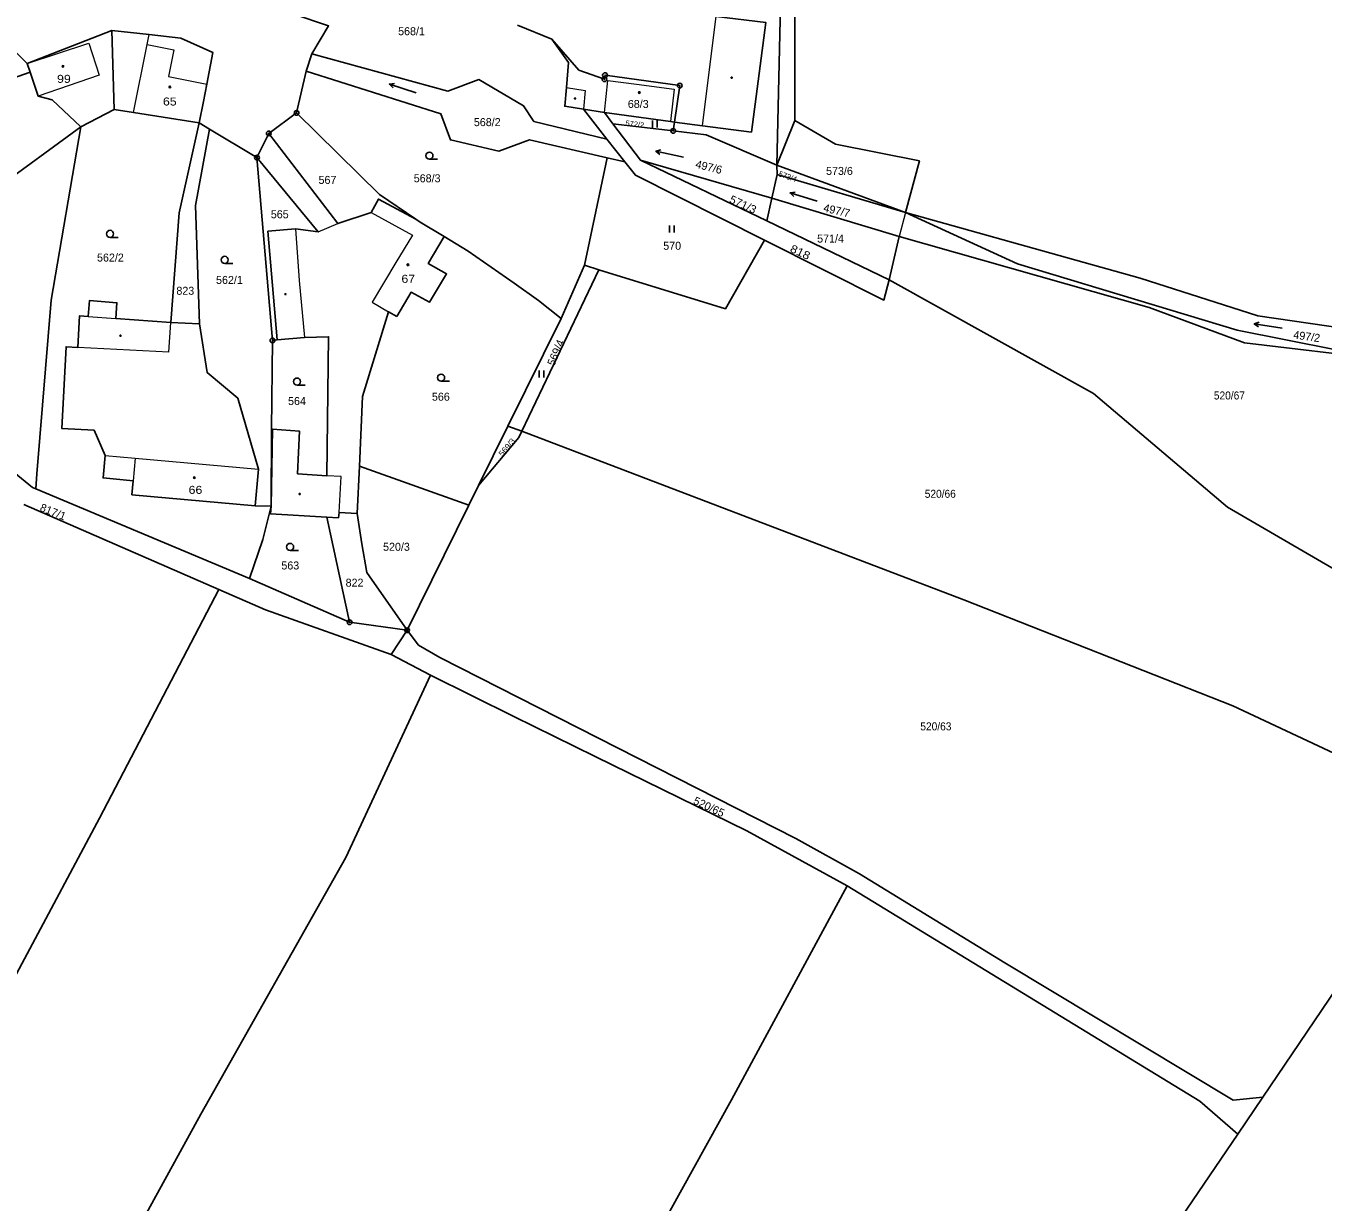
# Model space of a CAD drawing. Extents: x -687135 to -684370, y -1007309 to -1005782.
# Drawn here: x -685196.4 to -684920.8, y -1006924.3 to -1006674.4 of the extents above; entities that cross this region are included whole.
import ezdxf
from ezdxf.enums import TextEntityAlignment as Align

# ---------------------------------------------------------------- set-up
doc = ezdxf.new("R2010")
doc.units = 0
doc.header["$LTSCALE"] = 0.68
for name, color, linetype, lineweight in [('1', 7, 'Continuous', 25), ('3', 7, 'Continuous', 25), ('4', 7, 'Continuous', 13), ('5', 7, 'Continuous', 25), ('8', 7, 'Continuous', 25)]:
    doc.layers.add(name, color=color, linetype=linetype, lineweight=lineweight)
doc.layers.add('2', color=7, linetype='Continuous')

msp = doc.modelspace()

# ---------------------------------------------------------------- linework, layer by layer
at = {"layer": '1'}
for p, q in [((-685178.14, -1006675.35), (-685177.65, -1006692.14)), ((-685135.67, -1006680.29), (-685136.86, -1006684.01)), ((-685195.49, -1006684.24), (-685193.82, -1006689.33)), ((-685136.86, -1006684.01), (-685138.92, -1006692.88)), ((-685073.5, -1006692.79), (-685077.96, -1006692.1)), ((-685071.69, -1006695.18), (-685073.5, -1006692.79)), ((-685036.85, -1006703.99), (-685033.04, -1006694.46)), ((-685159.63, -1006694.97), (-685157.43, -1006696.29)), ((-685147.32, -1006702.37), (-685157.43, -1006696.29)), ((-685058.88, -1006696.69), (-685071.69, -1006695.18)), ((-685077.71, -1006725.24), (-685072.9, -1006702.41)), ((-685009.5, -1006714.05), (-685036.85, -1006703.99)), ((-685009.5, -1006714.05), (-685036.82, -1006705.99)), ((-685039.02, -1006715.81), (-685037.94, -1006710.98)), ((-685037.94, -1006710.98), (-685010.85, -1006719.1)), ((-685010.85, -1006719.1), (-685013.02, -1006728.33)), ((-685074.68, -1006726.22), (-685091.06, -1006760.52)), ((-685082.72, -1006736.58), (-685077.71, -1006725.24)), ((-685077.71, -1006725.24), (-685074.68, -1006726.22)), ((-685143.04, -1006741.12), (-685144.04, -1006741.22)), ((-685091.06, -1006760.52), (-685094, -1006759.4)), ((-685102.33, -1006776.25), (-685125.54, -1006767.91)), ((-685194.34, -1006772.72), (-685148.92, -1006791.82)), ((-685196.87, -1006776.1), (-685155.44, -1006794.14)), ((-685147.73, -1006776.37), (-685144.31, -1006776.4)), ((-685115.44, -1006802.78), (-685112.98, -1006805.94)), ((-685110.47, -1006812.34), (-685118.82, -1006807.94)), ((-684938.9, -1006909.84), (-684933.6, -1006902.01)), ((-684952.13, -1006929.37), (-684938.9, -1006909.84))]:
    msp.add_line(p, q, dxfattribs=at)
for points in [[(-685133.76, -1006656.79), (-685139.71, -1006671.79), (-685132.11, -1006674.38), (-685135.67, -1006680.29)], [(-685059.06, -1006657.45), (-685058.68, -1006657.58), (-685036.17, -1006663.13), (-685033.04, -1006666.8), (-685033.04, -1006694.46)], [(-685053.98, -1006661.6), (-685036.02, -1006666.77), (-685036.85, -1006703.99)], [(-685042.21, -1006696.98), (-685039.23, -1006673.64), (-685049.72, -1006672.4), (-685049.41, -1006669.85), (-685055.2, -1006669.06)], [(-685091.94, -1006674.21), (-685084.65, -1006677.21), (-685078.93, -1006683.79)], [(-685196.12, -1006682.34), (-685200.74, -1006677.86), (-685200.27, -1006677.13)], [(-685178.14, -1006675.35), (-685196.12, -1006682.34), (-685195.49, -1006684.24)], [(-685158.71, -1006690.46), (-685158.01, -1006686.78), (-685156.73, -1006680), (-685163.52, -1006677), (-685170.22, -1006676.24), (-685178.14, -1006675.35)], [(-685077.96, -1006692.1), (-685081.91, -1006691.47), (-685081.59, -1006687.48), (-685081.12, -1006682.18), (-685084.65, -1006677.21)], [(-685135.67, -1006680.29), (-685106.75, -1006688.26), (-685100.16, -1006685.79), (-685090.66, -1006691.34), (-685088.49, -1006694.69), (-685072.96, -1006698.48), (-685077.96, -1006692.1)], [(-685195.49, -1006684.24), (-685227.55, -1006695.45), (-685221.81, -1006712.7), (-685243.9, -1006716.28), (-685252.71, -1006703.66), (-685270.46, -1006710.92)], [(-685136.86, -1006684.01), (-685108.25, -1006693.03), (-685106.21, -1006698.62), (-685095.92, -1006700.97), (-685089.39, -1006698.59), (-685072.9, -1006702.41)], [(-685078.93, -1006683.79), (-685073.5, -1006685.72), (-685073.37, -1006684.84), (-685057.48, -1006687.07), (-685058.61, -1006694.83)], [(-685193.82, -1006689.33), (-685190.85, -1006690.09), (-685184.75, -1006695.82), (-685177.65, -1006692.14)], [(-685177.65, -1006692.14), (-685173.59, -1006692.78), (-685159.63, -1006694.97), (-685158.71, -1006690.46)], [(-685113.59, -1006715.43), (-685121.27, -1006710.22), (-685138.92, -1006692.88), (-685144.82, -1006697.23)], [(-685073.5, -1006692.79), (-685059.43, -1006694.72), (-685058.61, -1006694.83), (-685058.88, -1006696.69)], [(-685033.04, -1006694.46), (-685024.41, -1006699.51), (-685006.57, -1006703.08), (-685009.5, -1006714.05)], [(-685270.46, -1006710.92), (-685268.32, -1006713.45), (-685239.42, -1006735.75), (-685184.75, -1006695.82)], [(-685194.34, -1006772.72), (-685194.13, -1006769.56), (-685191.06, -1006732.67), (-685184.75, -1006695.82)], [(-685165.61, -1006737.42), (-685163.89, -1006714.12), (-685159.63, -1006694.97)], [(-685157.43, -1006696.29), (-685160.4, -1006712.56), (-685159.54, -1006737.67)], [(-685123.07, -1006714.04), (-685130.14, -1006716.36), (-685144.82, -1006697.23), (-685147.32, -1006702.37)], [(-685039.46, -1006719.93), (-685014.13, -1006732.65), (-685013.02, -1006728.33), (-685039.02, -1006715.81), (-685065.85, -1006702.9), (-685071.69, -1006695.18)], [(-685036.85, -1006703.99), (-685051.85, -1006697.52), (-685058.88, -1006696.69)], [(-685058.61, -1006694.83), (-685052.69, -1006695.64), (-685042.21, -1006696.98)], [(-685072.9, -1006702.41), (-685069.15, -1006703.28), (-685072.96, -1006698.48)], [(-685147.32, -1006702.37), (-685134.32, -1006718.15), (-685139.16, -1006717.47), (-685144.99, -1006718.02), (-685143.04, -1006741.12)], [(-685144.31, -1006776.4), (-685144.23, -1006760.09), (-685144.04, -1006741.22), (-685147.32, -1006702.37)], [(-685039.46, -1006719.93), (-685066.91, -1006706.11), (-685069.15, -1006703.28)], [(-685065.85, -1006702.9), (-685037.94, -1006710.98), (-685036.82, -1006705.99), (-685036.85, -1006703.99)], [(-685113.59, -1006715.43), (-685121.53, -1006711.18), (-685123.07, -1006714.04)], [(-685107.56, -1006719.13), (-685112.63, -1006716.05), (-685113.59, -1006715.43)], [(-685009.5, -1006714.05), (-684959.69, -1006727.98), (-684934.64, -1006735.98), (-684908.91, -1006739.74), (-684871.46, -1006725.48)], [(-685009.5, -1006714.05), (-684985.7, -1006724.97), (-684939.07, -1006739.01), (-684907.65, -1006745.25)], [(-685117.64, -1006736.16), (-685114.57, -1006730.97), (-685110.67, -1006733.11), (-685107.04, -1006727.09), (-685110.94, -1006724.84), (-685107.56, -1006719.13)], [(-685087.53, -1006732.71), (-685092.68, -1006729.07), (-685102.47, -1006722.27), (-685107.56, -1006719.13)], [(-685010.85, -1006719.1), (-684957.75, -1006734.19), (-684937.52, -1006741.72), (-684907.65, -1006745.25)], [(-685074.68, -1006726.22), (-685047.77, -1006734.48), (-685039.46, -1006719.93)], [(-684881.02, -1006828.49), (-684888.86, -1006809.5), (-684895.88, -1006802.9), (-684941.13, -1006776.61), (-684969.61, -1006752.46), (-685013.02, -1006728.33)], [(-685165.61, -1006737.42), (-685177.33, -1006736.55), (-685177.08, -1006733.2), (-685182.91, -1006732.76), (-685183.16, -1006736.12), (-685185.03, -1006735.98), (-685185.37, -1006742.7), (-685187.88, -1006742.57), (-685188.77, -1006759.95), (-685181.92, -1006760.3), (-685179.6, -1006765.66), (-685180.03, -1006770.44), (-685173.63, -1006771.02), (-685173.9, -1006774.01), (-685147.73, -1006776.37)], [(-685102.33, -1006776.25), (-685100.26, -1006772.07), (-685094, -1006759.4), (-685082.72, -1006736.58), (-685087.53, -1006732.71)], [(-685239.42, -1006735.75), (-685239.28, -1006735.88), (-685219.19, -1006752.8), (-685194.99, -1006772.45), (-685194.34, -1006772.72)], [(-685125.54, -1006767.91), (-685124.88, -1006753.15), (-685119.41, -1006735.11), (-685117.64, -1006736.16)], [(-685147.73, -1006776.37), (-685147.03, -1006768.6), (-685151.37, -1006753.5), (-685157.88, -1006748.05), (-685159.54, -1006737.67), (-685165.61, -1006737.42)], [(-685143.04, -1006741.12), (-685137.22, -1006740.57), (-685132.11, -1006740.42), (-685132.46, -1006769.96), (-685138.68, -1006769.57)], [(-685144.04, -1006760.1), (-685144.31, -1006776.4), (-685144.42, -1006778.06), (-685132.48, -1006778.74), (-685130, -1006778.88)], [(-685138.68, -1006769.57), (-685138.27, -1006760.52), (-685144.04, -1006760.1)], [(-685091.06, -1006760.52), (-685091.68, -1006761.83), (-685100.26, -1006772.07)], [(-684890.09, -1006842.2), (-684940, -1006818.88), (-684997.11, -1006796.31), (-685091.06, -1006760.52)], [(-685130, -1006778.88), (-685129.89, -1006777.78), (-685126.04, -1006777.98), (-685125.54, -1006767.91)], [(-685148.92, -1006791.82), (-685146.1, -1006783.5), (-685144.31, -1006776.4)], [(-685126.04, -1006777.98), (-685125.07, -1006784.4), (-685123.97, -1006790.52), (-685115.44, -1006802.78), (-685102.33, -1006776.25)], [(-685148.92, -1006791.82), (-685127.63, -1006801.1), (-685132.48, -1006778.74)], [(-685301.77, -1007070.79), (-685288.08, -1007040.77), (-685248.53, -1006968.29), (-685233.07, -1006943.13), (-685224.8, -1006928.93), (-685222.62, -1006924.15), (-685216.83, -1006911.45), (-685212.76, -1006902.52), (-685180.81, -1006842.75), (-685155.44, -1006794.14)], [(-685155.44, -1006794.14), (-685145.51, -1006798.46), (-685118.82, -1006807.94)], [(-685118.82, -1006807.94), (-685115.44, -1006802.78), (-685127.63, -1006801.1)], [(-685112.98, -1006805.94), (-685108.45, -1006808.58), (-685032.83, -1006847.04), (-685019.31, -1006854.52), (-684988.39, -1006873.48), (-684939.93, -1006902.67), (-684933.6, -1006902.01)], [(-685110.47, -1006812.34), (-685128.43, -1006851.09), (-685159.24, -1006905.6), (-685171.68, -1006928.22), (-685174.11, -1006932.29), (-685189.11, -1006951.99), (-685235.44, -1007020.02), (-685254.36, -1007053.37), (-685271.73, -1007082.37)], [(-685021.9, -1006857.13), (-685043.27, -1006845.39), (-685075.49, -1006829.59), (-685092.72, -1006821.13), (-685110.47, -1006812.34)], [(-684933.6, -1006902.01), (-684916.38, -1006876.58), (-684890.09, -1006842.2)], [(-685021.9, -1006857.13), (-685046.48, -1006902.6), (-685078.16, -1006959.76), (-685088.34, -1006979.18), (-685090.14, -1006982.62), (-685099.65, -1007000.57), (-685102.53, -1007005.79), (-685127.65, -1007045.71), (-685161.8, -1007101.88), (-685175.89, -1007128.8), (-685177.25, -1007132.97)], [(-684938.9, -1006909.84), (-684946.95, -1006902.83), (-685021.9, -1006857.13)]]:
    msp.add_lwpolyline(points, dxfattribs=at)
at = {"layer": '3'}
for p, q in [((-685119.187, -1006686.76), (-685118.103, -1006686.585)), ((-685063.291, -1006695.97), (-685063.291, -1006694.47)), ((-685062.29, -1006695.97), (-685062.29, -1006694.47)), ((-685110.683, -1006702.7), (-685108.933, -1006702.7)), ((-685062.539, -1006701.014), (-685061.479, -1006700.727)), ((-685034.033, -1006709.88), (-685032.952, -1006709.686)), ((-685178.543, -1006719.32), (-685176.793, -1006719.32)), ((-685059.681, -1006718.26), (-685059.681, -1006716.76)), ((-685058.68, -1006718.26), (-685058.68, -1006716.76)), ((-685154.173, -1006724.84), (-685152.423, -1006724.84)), ((-684935.419, -1006737.7), (-684934.375, -1006737.357)), ((-685087.381, -1006749.09), (-685087.381, -1006747.59)), ((-685086.38, -1006749.09), (-685086.38, -1006747.59)), ((-685138.803, -1006750.7), (-685137.053, -1006750.7)), ((-685108.193, -1006749.87), (-685106.443, -1006749.87)), ((-685140.283, -1006785.83), (-685138.533, -1006785.83))]:
    msp.add_line(p, q, dxfattribs=at)
for points in [[(-685113.48, -1006688.614), (-685119.187, -1006686.76), (-685118.412, -1006687.538)], [(-685056.671, -1006702.262), (-685062.539, -1006701.014), (-685061.688, -1006701.708)], [(-685028.295, -1006711.634), (-685034.033, -1006709.88), (-685033.245, -1006710.645)], [(-684929.493, -1006738.638), (-684935.419, -1006737.7), (-684934.532, -1006738.348)]]:
    msp.add_lwpolyline(points, dxfattribs=at)
for centre in [(-685110.6829, -1006701.9498), (-685178.5429, -1006718.5698), (-685154.1729, -1006724.0898), (-685138.8029, -1006749.9498), (-685108.1929, -1006749.1198), (-685140.2829, -1006785.0798)]:
    msp.add_circle(centre, 0.75, dxfattribs=at)
at = {"layer": '4'}
for p, q in [((-685196.12, -1006682.34), (-685183.08, -1006678.05)), ((-685073.5, -1006692.79), (-685072.74, -1006685.98)), ((-685072.74, -1006685.98), (-685066.66, -1006686.78)), ((-685066.66, -1006686.78), (-685058.67, -1006687.83)), ((-685058.67, -1006687.83), (-685059.43, -1006694.72)), ((-685134.32, -1006718.15), (-685130.14, -1006716.36)), ((-685123.07, -1006714.04), (-685114.31, -1006718.84)), ((-685009.5, -1006714.05), (-685010.85, -1006719.1)), ((-685114.31, -1006718.84), (-685117.84, -1006724.68)), ((-685117.84, -1006724.68), (-685122.88, -1006733.06)), ((-685122.88, -1006733.06), (-685119.41, -1006735.11)), ((-685183.16, -1006736.12), (-685177.33, -1006736.55)), ((-685166.07, -1006743.69), (-685165.61, -1006737.42)), ((-685166.07, -1006743.69), (-685185.37, -1006742.7)), ((-685173.2, -1006766.24), (-685147.03, -1006768.6)), ((-685129.45, -1006770.15), (-685132.46, -1006769.96)), ((-685129.89, -1006777.78), (-685129.45, -1006770.15))]:
    msp.add_line(p, q, dxfattribs=at)
for points in [[(-685052.69, -1006695.64), (-685051.81, -1006688.73), (-685049.72, -1006672.4)], [(-685173.59, -1006692.78), (-685170.64, -1006678.3), (-685170.22, -1006676.24)], [(-685183.08, -1006678.05), (-685180.84, -1006684.85), (-685193.82, -1006689.33)], [(-685170.64, -1006678.3), (-685164.96, -1006679.46), (-685166.11, -1006685.13), (-685158.01, -1006686.78)], [(-685081.59, -1006687.48), (-685077.59, -1006688.13), (-685077.96, -1006692.1)], [(-685139.16, -1006717.47), (-685138.37, -1006728.49), (-685137.22, -1006740.57)], [(-685179.6, -1006765.66), (-685173.2, -1006766.24), (-685173.63, -1006771.02)]]:
    msp.add_lwpolyline(points, dxfattribs=at)
at = {"layer": '5'}
for centre, radius in [((-685188.5268, -1006682.9892), 0.175), ((-685046.4748, -1006685.3894), 0.1225), ((-685165.8368, -1006687.3592), 0.175), ((-685066.0768, -1006688.5392), 0.175), ((-685079.7548, -1006689.8094), 0.1225), ((-685115.2568, -1006725.1392), 0.175), ((-685141.2548, -1006731.3794), 0.1225), ((-685176.3148, -1006740.1894), 0.1225), ((-685160.6268, -1006770.3592), 0.175), ((-685138.2648, -1006773.8494), 0.1225)]:
    msp.add_circle(centre, radius, dxfattribs=at)
at = {"layer": '8'}
for centre, radius in [((-685073.5, -1006685.7199), 0.5), ((-685073.37, -1006684.8399), 0.5), ((-685073.5, -1006685.7199), 0.0303), ((-685073.37, -1006684.8399), 0.0303), ((-685057.48, -1006687.0699), 0.5), ((-685057.48, -1006687.0699), 0.0303), ((-685138.92, -1006692.8799), 0.5), ((-685138.92, -1006692.8799), 0.0303), ((-685144.82, -1006697.2299), 0.5), ((-685144.82, -1006697.2299), 0.0303), ((-685058.88, -1006696.6899), 0.5), ((-685058.88, -1006696.6899), 0.0303), ((-685147.32, -1006702.3699), 0.5), ((-685147.32, -1006702.3699), 0.0303), ((-685144.04, -1006741.2199), 0.5), ((-685144.04, -1006741.2199), 0.0303), ((-685127.63, -1006801.0999), 0.5), ((-685127.63, -1006801.0999), 0.0303), ((-685115.44, -1006802.7799), 0.5), ((-685115.44, -1006802.7799), 0.0303)]:
    msp.add_circle(centre, radius, dxfattribs=at)

# ---------------------------------------------------------------- texts
at = {"layer": '2'}
for s, p in [('568/1', (-685117.33, -1006676.36)), ('568/2', (-685101.24, -1006695.679)), ('573/6', (-685026.4, -1006706.049)), ('567', (-685134.24, -1006707.96)), ('568/3', (-685114.01, -1006707.61)), ('565', (-685144.38, -1006715.26)), ('571/4', (-685028.3, -1006720.419)), ('570', (-685061, -1006721.95)), ('562/2', (-685181.31, -1006724.46)), ('562/1', (-685156.02, -1006729.21)), ('823', (-685164.45, -1006731.51)), ('566', (-685110.15, -1006754.02)), ('564', (-685140.72, -1006754.94)), ('520/3', (-685120.53, -1006785.91)), ('563', (-685142.14, -1006789.88)), ('822', (-685128.49, -1006793.539))]:
    msp.add_text(s, height=1.7, dxfattribs=at).set_placement(p)
for s, width, p in [('99', 1.15, (-685189.8, -1006686.48)), ('65', 1.15, (-685167.3, -1006691.299)), ('67', 1.15, (-685116.63, -1006728.97)), ('520/67', 0.95, (-684944, -1006753.76)), ('66', 1.15, (-685161.85, -1006773.82)), ('520/66', 0.95, (-685005.43, -1006774.65)), ('520/63', 0.95, (-685006.37, -1006824.07))]:
    msp.add_text(s, height=1.7, dxfattribs=dict(at, width=width)).set_placement(p)
msp.add_text('68/3', height=1.7, dxfattribs=at).set_placement((-685066.31, -1006691.82), align=Align.CENTER)
msp.add_text('572/2', height=1.139, rotation=353, dxfattribs=at).set_placement((-685067.1024, -1006695.8101), align=Align.CENTER)
for s, height, rotation, p in [('497/6', 1.7, 346, (-685054.265, -1006704.494)), ('573/4', 1.19, 341, (-685036.603, -1006706.302)), ('497/7', 1.7, 347, (-685027.091, -1006713.808)), ('569/4', 1.7, 67, (-685084.157, -1006746.762)), ('497/2', 1.7, 352, (-684927.198, -1006740.801)), ('817/1', 1.7, 338, (-685193.608, -1006777.368)), ('520/65', 1.7, 335, (-685054.779, -1006839.62))]:
    msp.add_text(s, height=height, rotation=rotation, dxfattribs=at).set_placement(p)
for s, height, rotation, width, p in [('571/3', 1.7, 335, 1.05, (-685047.109, -1006711.83)), ('818', 1.7, 335, 1.15, (-685034.219, -1006722.31)), ('569/3', 1.19, 50, 1.1, (-685095.184, -1006765.982))]:
    msp.add_text(s, height=height, rotation=rotation, dxfattribs=dict(at, width=width)).set_placement(p)

doc.saveas('drawing.dxf')
